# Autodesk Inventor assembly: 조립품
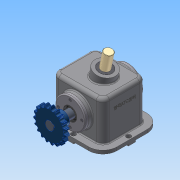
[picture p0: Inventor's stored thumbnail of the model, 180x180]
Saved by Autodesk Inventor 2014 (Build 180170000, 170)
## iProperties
Created: 2014-11
Part Number: 조립품
Document SubType Name: Assembly
Designer: user
Author: user
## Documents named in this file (13)
- C:\Users\user\Desktop\441122V1015\조립품.iam
- C:\Users\user\Desktop\441122V1015\본체.ipt
- C:\Users\user\Desktop\441122V1015\앞커버.ipt
- C:\Users\user\Desktop\441122V1015\뒤커버.ipt
- C:\Users\user\Desktop\441122V1015\편심축.ipt
- C:\Users\user\Desktop\441122V1015\베어링 6205.ipt
- C:\Users\user\Desktop\441122V1015\슬라이드.ipt
- C:\Users\user\Desktop\441122V1015\부시.ipt
- C:\Users\user\Desktop\441122V1015\오일실.ipt
- C:\Users\user\Desktop\441122V1015\키 8x8.ipt
- C:\Users\user\Desktop\441122V1015\5-체인 스프로킷.ipt
- C:\Users\user\Desktop\441122V1015\멈춤나사 M5x0.5.ipt
- C:\Users\user\Desktop\441122V1015\M4x0.5.ipt
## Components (9 placed, 2 different names)
1. 5-체인 스프로킷:1 — 각도:1
2. M4x0.5:1 — 각도:2
3. M4x0.5:2 — 각도:4
4. M4x0.5:3 — 각도:5
5. M4x0.5:4 — 각도:3
6. M4x0.5:5 — 각도:8
7. M4x0.5:6 — 각도:6
8. M4x0.5:7 — 각도:7
9. M4x0.5:8 — 각도:9
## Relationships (9: Angle 9)
- 각도:1 [Angle]: 5-체인 스프로킷:1
- 각도:2 [Angle]: M4x0.5:1
- 각도:3 [Angle]: M4x0.5:4
- 각도:4 [Angle]: M4x0.5:2
- 각도:5 [Angle]: M4x0.5:3
- 각도:6 [Angle]: M4x0.5:6
- 각도:7 [Angle]: M4x0.5:7
- 각도:8 [Angle]: M4x0.5:5
- 각도:9 [Angle]: M4x0.5:8
